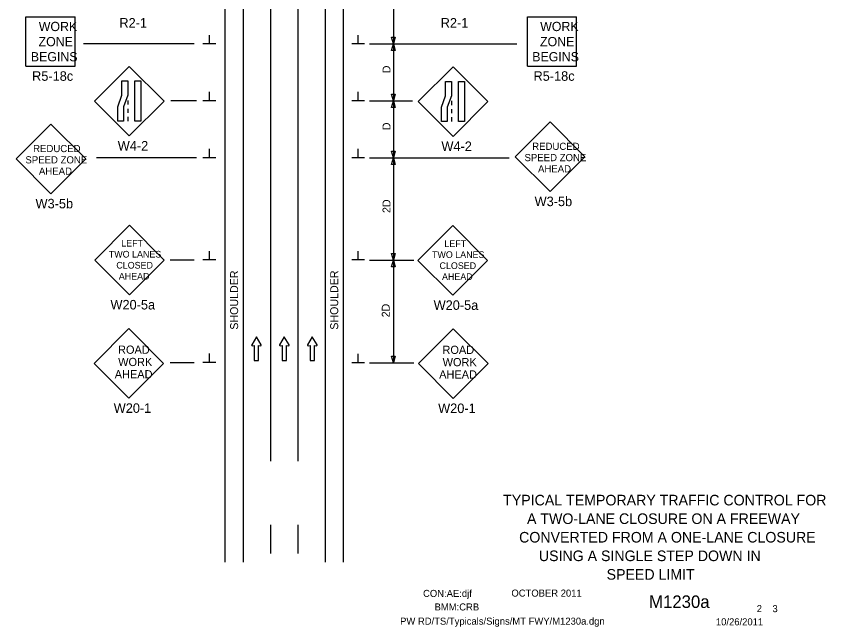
# Model space of a CAD drawing. Extents: x 16576 to 19508, y 5728 to 6974.
# Drawn here: x 17762 to 18473, y 5932 to 6468 of the extents above; entities that cross this region are included whole.
import ezdxf

# ---------------------------------------------------------------- set-up
doc = ezdxf.new("R2010")
doc.units = 0
for name, color, linetype in [('ALI_LEGAL_EX', 7, 'Continuous'), ('BORDER', 7, 'Continuous'), ('BORDER_SIGNAL_WO', 7, 'Continuous'), ('MT_SCRATCH_LEVEL_E', 7, 'Continuous'), ('PAVT_EDGE_EX', 7, 'Continuous'), ('TRAFFIC_SIGNS_PR', 7, 'Continuous'), ('TYPICAL_TEXT_DIMEN_PR', 7, 'Continuous')]:
    doc.layers.add(name, color=color, linetype=linetype)

msp = doc.modelspace()

# ---------------------------------------------------------------- linework, layer by layer
at = {"layer": 'ALI_LEGAL_EX'}
for p, q in [((17985.63, 6921.33), (17985.63, 6077.19)), ((18009.63, 6921.33), (18009.63, 6077.19))]:
    msp.add_line(p, q, dxfattribs=at)
for points in [[(17985.63, 6421.33), (17985.63, 6396.33)], [(18009.63, 6421.33), (18009.63, 6396.33)], [(17985.63, 6321.33), (17985.63, 6296.33)], [(18009.63, 6321.33), (18009.63, 6296.33)], [(17985.63, 6221.33), (17985.63, 6196.33)], [(18009.63, 6221.33), (18009.63, 6196.33)], [(17985.63, 6121.33), (17985.63, 6096.33)], [(18009.63, 6121.33), (18009.63, 6096.33)], [(17985.63, 6021.33), (17985.63, 5996.33)], [(18009.63, 6021.33), (18009.63, 5996.33)]]:
    msp.add_lwpolyline(points, dxfattribs=at)
at = {"layer": 'MT_SCRATCH_LEVEL_E'}
for p, q in [((17973.31, 6186.57), (17969.2, 6179.33)), ((17977.46, 6179.33), (17973.31, 6186.57)), ((17997.84, 6186.57), (17993.73, 6179.33)), ((18001.99, 6179.33), (17997.84, 6186.57)), ((18022.4, 6186.57), (18018.29, 6179.33)), ((18026.55, 6179.33), (18022.4, 6186.57)), ((17969.68, 6178.65), (17971.46, 6178.96)), ((17971.46, 6178.96), (17971.46, 6165.71)), ((17975.2, 6165.71), (17975.2, 6178.96)), ((17975.2, 6178.96), (17976.98, 6178.65)), ((17994.21, 6178.65), (17995.99, 6178.96)), ((17995.99, 6178.96), (17995.99, 6165.71)), ((17999.73, 6165.71), (17999.73, 6178.96)), ((17999.73, 6178.96), (18001.51, 6178.65)), ((18018.77, 6178.65), (18020.55, 6178.96)), ((18020.55, 6178.96), (18020.55, 6165.71)), ((18024.29, 6165.71), (18024.29, 6178.96)), ((18024.29, 6178.96), (18026.07, 6178.65)), ((17971.46, 6165.71), (17975.2, 6165.71)), ((17995.99, 6165.71), (17999.73, 6165.71)), ((18020.55, 6165.71), (18024.29, 6165.71))]:
    msp.add_line(p, q, dxfattribs=at)
for centre, start, end in [((17969.61, 6179.11), 150.42484, 279.96381), ((17977.05, 6179.11), 260.03619, 29.77312), ((17994.14, 6179.11), 150.42484, 279.96381), ((18001.58, 6179.11), 260.03619, 29.77312), ((18018.7, 6179.11), 150.42484, 279.96381), ((18026.14, 6179.11), 260.03619, 29.77312)]:
    msp.add_arc(centre, 0.463, start, end, dxfattribs=at)
at = {"layer": 'PAVT_EDGE_EX'}
for p, q in [((17945.63, 6921.33), (17945.63, 5988.51)), ((17961.63, 6921.33), (17961.63, 5988.51)), ((18033.63, 6921.33), (18033.63, 5988.51)), ((18049.63, 6921.33), (18049.63, 5988.51))]:
    msp.add_line(p, q, dxfattribs=at)
at = {"layer": 'TRAFFIC_SIGNS_PR'}
for p, q in [((17770.89, 6424.1), (17770.89, 6467.3)), ((17770.89, 6467.3), (17814.08, 6467.3)), ((17814.08, 6424.1), (17814.08, 6467.3)), ((18211.31, 6424.1), (18211.31, 6467.3)), ((18211.31, 6467.3), (18254.51, 6467.3)), ((18254.51, 6424.1), (18254.51, 6467.3)), ((17770.89, 6424.1), (17814.08, 6424.1)), ((17861.69, 6423.92), (17831.14, 6393.37)), ((17892.24, 6393.37), (17861.69, 6423.92)), ((18146, 6423.55), (18115.45, 6393)), ((18176.54, 6393), (18146, 6423.55)), ((18211.31, 6424.1), (18254.51, 6424.1)), ((17831.14, 6393.37), (17861.69, 6362.83)), ((17860.29, 6393.93), (17860.29, 6390.33)), ((17861.69, 6362.83), (17892.24, 6393.37)), ((18144.59, 6393.56), (18144.59, 6389.96)), ((17860.29, 6386.73), (17860.29, 6383.13)), ((18115.45, 6393), (18146, 6362.46)), ((18144.59, 6386.36), (18144.59, 6382.76)), ((18146, 6362.46), (18176.54, 6393)), ((17860.29, 6379.53), (17860.29, 6375.93)), ((18144.59, 6379.16), (18144.59, 6375.56)), ((17792.87, 6373.18), (17762.32, 6342.63)), ((17823.41, 6342.63), (17792.87, 6373.18)), ((18231.23, 6375.15), (18200.69, 6344.6)), ((18261.78, 6344.6), (18231.23, 6375.15)), ((18200.69, 6344.6), (18231.23, 6314.05)), ((18231.23, 6314.05), (18261.78, 6344.6)), ((17762.32, 6342.63), (17792.87, 6312.09)), ((17792.87, 6312.09), (17823.41, 6342.63)), ((17861.84, 6284.42), (17831.29, 6253.87)), ((17892.38, 6253.87), (17861.84, 6284.42)), ((18145.71, 6284.05), (18115.16, 6253.5)), ((18176.26, 6253.5), (18145.71, 6284.05)), ((17831.29, 6253.87), (17861.84, 6223.33)), ((17861.84, 6223.33), (17892.38, 6253.87)), ((18115.16, 6253.5), (18145.71, 6222.95)), ((18145.71, 6222.95), (18176.26, 6253.5)), ((17861.29, 6193.64), (17830.75, 6163.09)), ((17891.84, 6163.09), (17861.29, 6193.64)), ((18146.27, 6193.48), (18115.72, 6162.94)), ((18176.81, 6162.94), (18146.27, 6193.48)), ((17830.75, 6163.09), (17861.29, 6132.55)), ((17861.29, 6132.55), (17891.84, 6163.09)), ((18115.72, 6162.94), (18146.27, 6132.39)), ((18146.27, 6132.39), (18176.81, 6162.94))]:
    msp.add_line(p, q, dxfattribs=at)
for points in [[(17860.29, 6411.08), (17860.29, 6398.5), (17856.53, 6388.51), (17856.53, 6375.93), (17851.47, 6375.93), (17851.47, 6388.51), (17855.23, 6398.5), (17855.23, 6411.08)], [(17871.69, 6411.08), (17871.69, 6375.93), (17866.64, 6375.93), (17866.64, 6411.08)], [(18144.59, 6410.71), (18144.59, 6398.13), (18140.83, 6388.14), (18140.83, 6375.56), (18135.78, 6375.56), (18135.78, 6388.14), (18139.54, 6398.13), (18139.54, 6410.71)], [(18156, 6410.71), (18156, 6375.56), (18150.94, 6375.56), (18150.94, 6410.71)]]:
    msp.add_lwpolyline(points, close=True, dxfattribs=at)
at = {"layer": 'TYPICAL_TEXT_DIMEN_PR'}
for p, q in [((18093.63, 6493.63), (18093.63, 6443.63)), ((17932.02, 6443.63), (17932.02, 6451.41)), ((18062.76, 6443.63), (18062.76, 6451.41)), ((17918.58, 6443.63), (17821.42, 6443.63)), ((17937.64, 6443.63), (17926.39, 6443.63)), ((18068.38, 6443.63), (18057.13, 6443.63)), ((18072.63, 6443.63), (18202.12, 6443.63)), ((18093.63, 6443.63), (18092.06, 6449.49)), ((18092.06, 6449.49), (18093.63, 6449.49)), ((18092.06, 6437.77), (18093.63, 6443.63)), ((18093.63, 6449.49), (18095.2, 6449.49)), ((18095.2, 6449.49), (18093.63, 6443.63)), ((18093.63, 6443.63), (18095.2, 6437.77)), ((18093.63, 6443.63), (18093.63, 6393.63)), ((18093.63, 6437.77), (18092.06, 6437.77)), ((18095.2, 6437.77), (18093.63, 6437.77)), ((17932.02, 6393.63), (17932.02, 6401.41)), ((18062.76, 6393.63), (18062.76, 6401.41)), ((17920.56, 6393.63), (17898.06, 6393.63)), ((17937.64, 6393.63), (17926.39, 6393.63)), ((18068.38, 6393.63), (18057.13, 6393.63)), ((18072.63, 6393.63), (18110.31, 6393.63)), ((18093.63, 6393.63), (18092.06, 6399.49)), ((18092.06, 6399.49), (18093.63, 6399.49)), ((18092.06, 6387.77), (18093.63, 6393.63)), ((18093.63, 6399.49), (18095.2, 6399.49)), ((18095.2, 6399.49), (18093.63, 6393.63)), ((18093.63, 6393.63), (18093.63, 6343.63)), ((18093.63, 6393.63), (18095.2, 6387.77)), ((18093.63, 6387.77), (18092.06, 6387.77)), ((18095.2, 6387.77), (18093.63, 6387.77)), ((17932.02, 6343.63), (17932.02, 6351.41)), ((18062.76, 6343.63), (18062.76, 6351.41)), ((17920.56, 6343.63), (17832.96, 6343.63)), ((17937.64, 6343.63), (17926.39, 6343.63)), ((18068.38, 6343.63), (18057.13, 6343.63)), ((18072.63, 6343.63), (18195.39, 6343.63)), ((18093.63, 6343.63), (18092.06, 6349.49)), ((18092.06, 6349.49), (18093.63, 6349.49)), ((18092.06, 6337.77), (18093.63, 6343.63)), ((18093.63, 6349.49), (18095.2, 6349.49)), ((18095.2, 6349.49), (18093.63, 6343.63)), ((18093.63, 6343.63), (18093.63, 6253.63)), ((18093.63, 6343.63), (18095.2, 6337.77)), ((18093.63, 6337.77), (18092.06, 6337.77)), ((18095.2, 6337.77), (18093.63, 6337.77)), ((17932.02, 6253.95), (17932.02, 6261.74)), ((18062.76, 6253.95), (18062.76, 6261.74)), ((18093.63, 6253.63), (18092.06, 6259.49)), ((18092.06, 6259.49), (18093.63, 6259.49)), ((18093.63, 6259.49), (18095.2, 6259.49)), ((18095.2, 6259.49), (18093.63, 6253.63)), ((17918.58, 6253.63), (17897.44, 6253.63)), ((17937.64, 6253.95), (17926.39, 6253.95)), ((18068.38, 6253.95), (18057.13, 6253.95)), ((18072.63, 6253.63), (18111.63, 6253.63)), ((18092.06, 6247.77), (18093.63, 6253.63)), ((18093.63, 6253.63), (18093.63, 6163.63)), ((18093.63, 6253.63), (18095.2, 6247.77)), ((18093.63, 6247.77), (18092.06, 6247.77)), ((18095.2, 6247.77), (18093.63, 6247.77)), ((17932.02, 6163.9), (17932.02, 6171.68)), ((18062.76, 6163.63), (18062.76, 6171.41)), ((18093.63, 6163.63), (18092.06, 6169.49)), ((18092.06, 6169.49), (18093.63, 6169.49)), ((18093.63, 6169.49), (18095.2, 6169.49)), ((18095.2, 6169.49), (18093.63, 6163.63)), ((17918.58, 6163.63), (17897.44, 6163.63)), ((17937.64, 6163.9), (17926.39, 6163.9)), ((18068.38, 6163.63), (18057.13, 6163.63)), ((18072.63, 6163.63), (18111.63, 6163.63))]:
    msp.add_line(p, q, dxfattribs=at)

# ---------------------------------------------------------------- texts
at = {"layer": 'BORDER'}
for s, p in [('TYPICAL TEMPORARY TRAFFIC CONTROL FOR', (18190.04, 6038.42)), ('A TWO-LANE CLOSURE ON A FREEWAY', (18210.99, 6022.12)), ('CONVERTED FROM A ONE-LANE CLOSURE', (18204.06, 6005.82)), ('USING A SINGLE STEP DOWN IN ', (18221.42, 5989.52)), ('SPEED LIMIT', (18280.92, 5973.22))]:
    msp.add_text(s, height=9.3, dxfattribs=at).set_placement(p)
at = {"layer": 'BORDER_SIGNAL_WO'}
for s, height, p in [('CON:AE:djf  ', 6.2, (18119.69, 5958.06)), ('    OCTOBER 2011    ', 6.2, (18188.08, 5958.34)), ('    M1230a   ', 11, (18301.86, 5948.38)), ('BMM:CRB   ', 6.2, (18129.81, 5946.17)), (' 2    3 ', 6.2, (18410.45, 5944.7)), ('PW RD/TS/Typicals/Signs/MT FWY/M1230a.dgn      ', 6.2, (18099.55, 5933.71)), ('10/26/2011    ', 6.2, (18376.93, 5933.13))]:
    msp.add_text(s, height=height, dxfattribs=at).set_placement(p)
at = {"layer": 'TRAFFIC_SIGNS_PR'}
for s, height, p in [('R2-1', 8.37, (17852.97, 6457.97)), ('R2-1', 8.37, (18135.21, 6457.97)), ('WORK', 8.119, (17782.14, 6454.88)), ('WORK', 8.119, (18222.56, 6454.88)), ('ZONE', 8.119, (17782, 6441.6)), ('ZONE', 8.119, (18222.43, 6441.6)), ('BEGINS', 8.119, (17775.17, 6428.31)), ('BEGINS', 8.119, (18215.6, 6428.31)), ('R5-18c', 8.37, (17776.3, 6411.23)), ('R5-18c', 8.37, (18216.72, 6411.23)), ('W4-2', 8.37, (17851.52, 6349.96)), ('W4-2', 8.37, (18135.83, 6349.59)), ('REDUCED', 6.3, (17777.18, 6348.61)), ('REDUCED', 6.3, (18215.55, 6350.57)), ('SPEED ZONE', 6.3, (17770.42, 6338.7)), ('SPEED ZONE', 6.3, (18208.79, 6340.67)), ('AHEAD', 6.3, (18220.67, 6330.77)), ('AHEAD', 6.3, (17782.3, 6328.81)), ('W3-5b', 8.37, (17779.31, 6299.22)), ('W3-5b', 8.37, (18217.68, 6301.18)), ('LEFT', 5.85, (17854.57, 6265.72)), ('LEFT', 5.85, (18138.44, 6265.35)), ('TWO LANES', 5.85, (17843.68, 6256.05)), ('TWO LANES', 5.85, (18127.55, 6255.68)), ('CLOSED', 5.85, (17850.27, 6246.37)), ('CLOSED', 5.85, (18134.14, 6246)), ('AHEAD', 5.85, (17852.46, 6236.7)), ('AHEAD', 5.85, (18136.33, 6236.33)), ('W20-5a', 8.37, (17845.12, 6210.46)), ('W20-5a', 8.37, (18128.99, 6210.09)), ('ROAD', 7.2, (17851.78, 6171.57)), ('ROAD', 7.2, (18136.75, 6171.41)), ('WORK', 7.2, (17851.9, 6160.77)), ('WORK', 7.2, (18136.87, 6160.61)), ('AHEAD', 7.2, (17848.87, 6149.97)), ('AHEAD', 7.2, (18133.85, 6149.82)), ('W20-1', 8.37, (17847.98, 6119.68)), ('W20-1', 8.37, (18132.96, 6119.52))]:
    msp.add_text(s, height=height, dxfattribs=at).set_placement(p)
at = {"layer": 'TYPICAL_TEXT_DIMEN_PR'}
for s, p in [('D', (18091.08, 6417.85)), ('D', (18091.08, 6367.85)), ('2D', (18091.08, 6295.15)), ('SHOULDER', (17957.25, 6192.68)), ('SHOULDER', (18045.15, 6192.68)), ('2D', (18090.43, 6203.54))]:
    msp.add_text(s, height=7, rotation=90, dxfattribs=at).set_placement(p)

doc.saveas('drawing.dxf')
